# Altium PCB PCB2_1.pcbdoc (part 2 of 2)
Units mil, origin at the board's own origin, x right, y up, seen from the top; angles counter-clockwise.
Board outline 4577.16 x 3522.49 mil, 4 copper layers (Top Layer, Inner1, Inner2, Bottom Layer); 102 components, 86 nets, 382 pads, 182 vias.
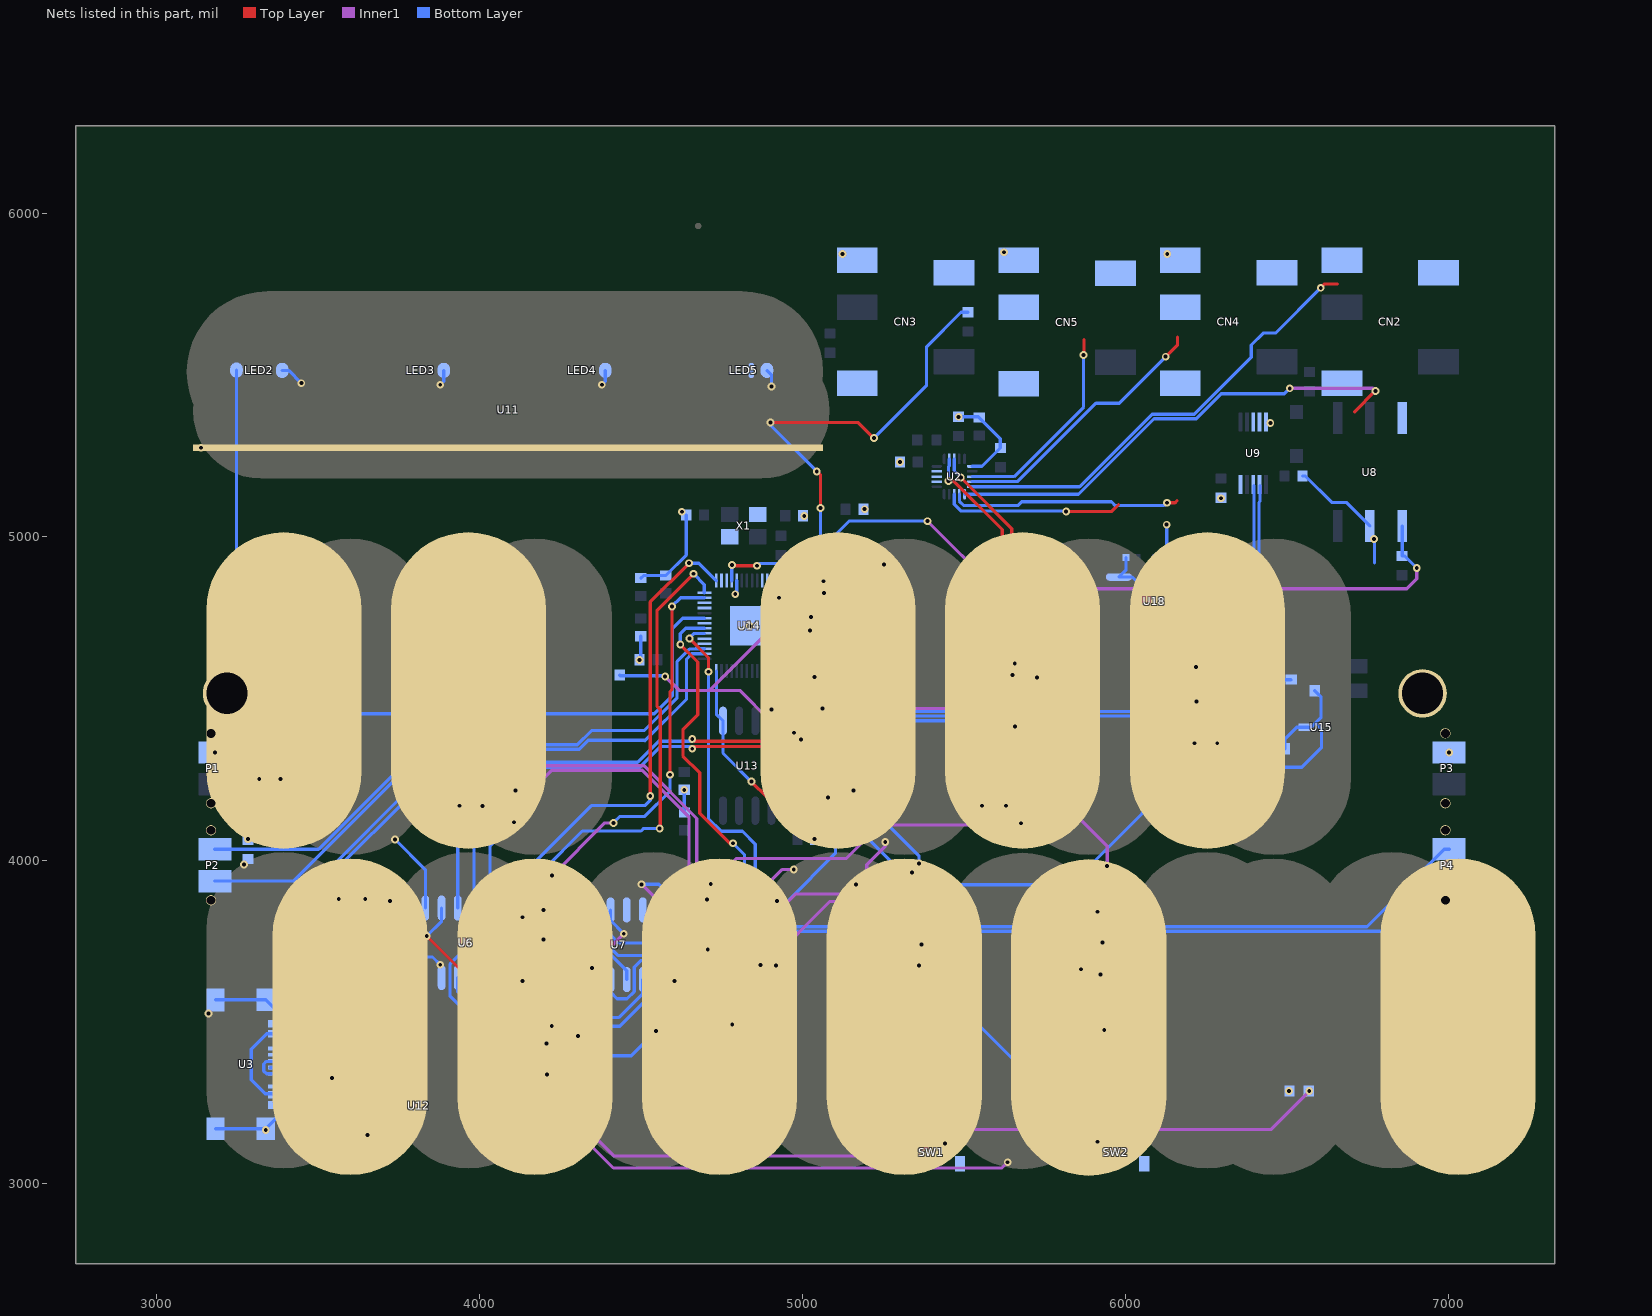
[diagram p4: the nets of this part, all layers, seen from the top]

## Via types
v1: diameter 24.02, hole 12.01, Top Layer to Bottom Layer, 182 vias

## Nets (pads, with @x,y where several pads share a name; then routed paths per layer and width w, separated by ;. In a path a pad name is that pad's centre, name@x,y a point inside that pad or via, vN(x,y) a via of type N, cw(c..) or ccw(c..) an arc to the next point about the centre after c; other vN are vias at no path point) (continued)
ADC-CS-1: U7.10 U14.30 | length 1660.7
  Inner1 w10: v1(4706.64,3722.97) 4770.64,3722.97 v1(4920.64,3872.97)
  Bottom Layer w10: U7.10@4555.64,3630.27 4555.64,3674.07 4604.54,3722.97 v1(4706.64,3722.97) ; v1(4920.64,3872.97) 4953.64,3872.97 5101.64,4020.97 5101.64,4090.97 5090.89,4101.72 5061.25,4101.72 5031.63,4131.34 5031.63,4405.16 5021.63,4415.16 5021.63,4511.77 5067.23,4557.38 5067.23,4769.56 5025.19,4811.59 U14.30@4975.41,4811.59
AS_SIG: K11.2 R28.2 U7.3 | length 2793.5
  Inner1 w10: v1(4501.64,3924.97) 4673.64,3752.97 4673.64,3708.97 4683.64,3698.97 4782.64,3698.97 4978.64,3894.97 5136.64,3894.97 v1(5165.64,3923.97)
  Bottom Layer w10: U7.3@4355.64,3845.67 4355.64,3823.97 4404.64,3774.97 4404.64,3768.43 4429.87,3743.2 4565.31,3743.2 4587.13,3765.01 4635.69,3765.01 4652.64,3781.97 4652.64,3868.97 4625.64,3895.97 4583.64,3895.97 4554.64,3924.97 v1(4501.64,3924.97) ; v1(5165.64,3923.97) 5830.64,3923.97 R28.2@6268.14,4361.46
  other v1: 6283.39,4361.46
B_SIG: K12.2 R27.2 U7.4 | length 3512.9
  Inner1 w10: v1(4446.64,3771.97) 4379.64,3704.97 4075.64,3704.97 4043.64,3672.97 4043.64,3456.97 4416.64,3083.97 5267.64,3083.97 5326.64,3142.97 5399.64,3142.97 5422.64,3165.97 6449.14,3165.97 v1(6568.14,3284.97)
  Bottom Layer w10: U7.4@4405.64,3845.67 4405.64,3812.97 v1(4446.64,3771.97)
BOOT: D3.1 SW2.2 U14.32 | length 2480.7
  Top Layer w10: v1(5036.64,4566.97) 5036.64,4493.97 v1(5061.64,4468.97) ; v1(5912.64,3839.97) 5927.64,3824.97 v1(5927.64,3744.97)
  Inner1 w10: v1(5061.64,4468.97) 5516.64,4468.97 5942.64,4042.97 v1(5942.64,3981.97)
  Bottom Layer w10: U14.32@4975.41,4780.09 5031.52,4780.09 5053.23,4758.38 5053.23,4583.56 v1(5036.64,4566.97) ; v1(5912.64,3839.97) 5942.64,3869.97 v1(5942.64,3981.97) ; v1(5927.64,3744.97) 6034.58,3638.03 6034.58,3215.76 ; D3.1@5980.81,3220.97 6029.38,3220.97 6034.58,3215.76 ; SW2.2@6034.58,3132.09 6034.58,3215.76
C_SIG: K1.2 R21.2 U6.1 | length 305.9
  Bottom Layer w10: v1(3564.64,3878.97) 3623.64,3937.97 3743.64,3937.97 3782.64,3898.97 U6.1@3782.64,3851.67
  other v1: 3271.41,3986.26
CAP0: U2.8 | length 643.8
  Top Layer w10: v1(5869.64,5562.97) 5870.64,5563.97 5870.64,5610.97
  Bottom Layer w10: U2.8@5524.28,5186.97 5654.64,5186.97 5869.64,5401.97 v1(5869.64,5562.97)
CAP1: U2.9 | length 834.9
  Top Layer w10: v1(6123.64,5557.97) 6160.64,5594.97 6160.64,5617.97
  Bottom Layer w10: U2.9@5524.28,5171.22 5664.89,5171.22 5907.64,5413.97 5979.64,5413.97 v1(6123.64,5557.97)
CAP2: U2.10 | length 1412.5
  Top Layer w10: v1(6603.64,5770.97) 6615.64,5782.97 6654.64,5782.97
  Bottom Layer w10: U2.10@5524.28,5155.47 5857.14,5155.47 6081.64,5379.97 6212.64,5379.97 6388.64,5555.97 6388.64,5593.97 6425.64,5630.97 6463.64,5630.97 v1(6603.64,5770.97)
CAP3: U2.11 | length 1502
  Top Layer w10: 6708.64,5386.97 6708.64,5387.97 v1(6772.64,5451.97)
  Inner1 w10: v1(6507.64,5459.97) 6764.64,5459.97 v1(6772.64,5451.97)
  Bottom Layer w10: U2.11@5501.15,5132.34 5853.81,5132.34 6087.44,5365.97 6218.44,5365.97 6295.44,5442.97 6490.64,5442.97 v1(6507.64,5459.97)
CAP4: U2.12 | length 716.5
  Top Layer w10: v1(6127.64,5105.97) 6152.64,5105.97 6158.64,5111.97
  Bottom Layer w10: U2.12@5485.4,5132.34 5485.4,5111.1 5499.53,5096.97 5666.42,5096.97 5678.42,5108.97 5955.9,5108.97 5967.9,5096.97 6118.64,5096.97 v1(6127.64,5105.97)
CAP5: U2.13 | length 557.2
  Top Layer w10: v1(5815.64,5078.97) 5956.64,5078.97 5977.64,5099.97
  Bottom Layer w10: U2.13@5469.65,5132.34 5469.65,5100.96 5490.64,5079.97 5814.64,5079.97 v1(5815.64,5078.97)
CS_SIG: K2.2 R14.2 U6.2 | length 251.2
  Bottom Layer w10: v1(3738.64,4063.97) 3832.64,3969.97 U6.2@3832.64,3851.67
  other v1: 3384.42,4251.29
D+: R35.2 U3.A6 U3.B6 | length 2589.7
  Top Layer w10: v1(4658.64,4374.65) 4665.64,4367.65 4957.33,4367.65 4973.64,4383.97 v1(4973.64,4393.87)
  Bottom Layer w10: U3.B6@3374.57,3397.5 3406.11,3397.5 3417.64,3385.97 3417.64,3364.97 3411.64,3358.97 3375.41,3358.97 U3.A6@3374.57,3358.13 3351.5,3358.11 3351.5,3357.3 3384.57,3357.3 3386,3355.87 3504.64,3355.87 3564.64,3415.87 3564.64,3754.97 3511.95,3807.65 3511.95,3948.91 3805.01,4241.97 4066.64,4241.97 4127.33,4302.65 4489.33,4302.65 4554.33,4367.65 4651.64,4367.65 v1(4658.64,4374.65)
D-: R36.2 U3.A7 U3.B7 | length 2704.7
  Top Layer w10: v1(4658.64,4344.65) 4665.64,4351.65 4963.95,4351.65 4984.95,4372.65 v1(4994.85,4372.65)
  Bottom Layer w10: U3.A7@3374.57,3377.81 3373.73,3376.97 3340.64,3376.97 3332.64,3368.97 3332.64,3346.97 3341.17,3338.44 U3.B7@3374.57,3338.44 3384.57,3338.44 3386,3339.87 3511.27,3339.87 3580.64,3409.24 3580.64,3761.59 3527.95,3814.28 3527.95,3942.28 3811.64,4225.97 4073.27,4225.97 4133.95,4286.65 4495.95,4286.65 4560.95,4351.65 4651.64,4351.65 v1(4658.64,4344.65) ; R36.2@4978.69,4509.92 5002.64,4485.97 5002.64,4380.44 v1(4994.85,4372.65)
D_SIG: K3.2 R15.2 U6.3 | length 544.3
  Top Layer w10: v1(3836.64,3764.97) 4086.64,3514.97 K3.2@4171.64,3514.97
  Bottom Layer w10: v1(3836.64,3764.97) 3882.64,3810.97 U6.3@3882.64,3851.67
  other v1: 3722.64,3872.97
DS_SIG: K4.2 R16.2 U6.4 | length 344.4
  Bottom Layer w10: U6.4@3932.64,3851.67 3932.64,4053.97 3999.8,4121.12 R16.2@3999.8,4168.29
  other v1: 4009.64,4166.97
E_SIG: K5.2 R17.2 U6.5 | length 1388.8
  Inner1 w10: v1(4111.64,4214.97) 4188.64,4291.97 4509.44,4291.97 4672.64,4128.77 4672.64,3909.97 v1(4704.64,3877.97)
  Bottom Layer w10: U6.5@3982.64,3851.67 3982.64,4054.97 4111.64,4183.97 v1(4111.64,4214.97) ; R17.2@4266.55,3432.29 4281.97,3432.29 v1(4304.64,3454.97)
F0: U7.5
F1: U7.6
F2: U7.7
F3: U7.8
F_SIG: K6.2 R18.2 U6.6 | length 1693.2
  Inner1 w10: v1(4106.64,4116.97) 4136.64,4146.97 4136.64,4190.97 4223.63,4277.95 4503.66,4277.95 4648.84,4132.77 4648.84,3873.77 4744.64,3777.97 4937.64,3970.97 v1(4972.64,3970.97)
  Bottom Layer w10: U6.6@4032.64,3851.67 4032.64,4042.97 v1(4106.64,4116.97)
  other v1: 4869.64,3674.97
FS_SIG: K7.2 R19.2 U6.7 | length 2120.4
  Inner1 w10: v1(4546.64,3470.97) 4598.64,3522.97 4716.64,3522.97 4832.64,3638.97 4873.64,3638.97 4893.64,3658.97 4893.64,3681.29 5084.21,3871.86 5147.37,3871.86 5198.5,3922.99 5198.5,3986.15 5255.64,4043.29 v1(5255.64,4055.97)
  Bottom Layer w10: U6.7@4082.64,3851.67 4067.64,3836.67 4067.64,3799.97 4031.64,3799.97 3908.64,3676.97 3908.64,3579.97 4094.33,3394.28 4469.95,3394.28 v1(4546.64,3470.97)
  other v1: 5554.64,4168.29
G_SIG: K8.2 R20.2 U6.8 | length 2218
  Inner1 w10: v1(4132.64,3822.97) 4014.64,3704.97 4014.64,3446.97 4414.64,3046.97 5616.64,3046.97 v1(5634.64,3064.97)
  other v1: 5861.13,3662.04
GND: C1.1 C2.2 C8.1 C9.2 C12.1 C13.1 C14.2 C15.2 C16.2 C17.2 C18.1 C19.1 C20.1 C21.1 C22.1 C23.1 C24.1 C25.1 C27.2 CN3.1 CN4.1 CN5.1 LED2.4 LED3.4 LED4.4 LED5.4 P1.1 P3.1 R1.1 R2.1 R8.1 R9.1 R14.1 R15.1 R16.1 R17.1 R18.1 R19.1 R20.1 R21.1 R22.1 R27.1 R28.1 R29.1 R30.1 R38.1 R39.1 R42.1 SW1.2 SW2.1 U2.6 U3.12 U3.13 U3.14 U3.15 U3.A1B12 U3.A12B1 U6.9 U6.14 U7.9 U7.14 U8.5 U9.10 U11.3 U12.1 U13.4 U14.19 U14.57 U15.2 U18.4 | length 4224.7
  Bottom Layer w10: U3.14@3182.72,3168.36 U3.12@3338.63,3168.36 3374.57,3204.3 U3.A1B12@3374.57,3241.99 ; U3.15@3182.72,3567.57 U3.13@3338.63,3567.58 ; U3.13@3338.63,3567.58 3374.57,3531.64 U3.A12B1@3374.57,3493.96 3431.27,3493.96 R9.1@3448.23,3510.91 ; LED2.4@3389.51,5515.47 3409.14,5515.47 v1(3448.64,5475.97) ; C8.1@3644.64,3467.41 3644.64,3587.97 3756.64,3699.97 3854.64,3699.97 v1(3878.64,3675.97) ; v1(3878.64,5470.97) 3889.51,5481.84 LED3.4@3889.51,5515.47 ; C9.2@4147.2,3312.97 4185.64,3312.97 v1(4208.64,3335.97) ; v1(4378.64,5470.97) 4389.51,5481.84 LED4.4@4389.51,5515.47 ; v1(4495.52,4619.53) 4499.08,4623.09 C19.1@4499.08,4692.53 ; C21.1@4499.64,4872.53 4507.77,4880.65 C20.1@4576.82,4880.65 4640.08,4943.91 C14.2@4640.08,5067.97 ; v1(4633.64,4217.41) 4633.64,4148.07 C23.1@4634.5,4147.21 ; v1(4791.64,4822.97) 4796.27,4827.6 U14.19@4796.27,4864.74 ; LED5.4@4889.51,5515.47 4903.64,5501.34 v1(4903.64,5465.97) ; C17.2@5245.2,4844.97 5245.2,4852.6 C16.2@5181.76,4916.04 5250.57,4916.04 v1(5251.64,4914.97) ; v1(5483.07,5371.78) 5544.39,5371.78 C1.1@5546.64,5369.53 5611.98,5304.19 R1.1@5611.98,5275.29 5555.16,5218.47 U2.6@5524.28,5218.47 ; v1(5650,4572.46) 5626.64,4595.82 5626.64,4618.97 5692.35,4684.68 R42.1@5903.6,4684.68 ; v1(6126.64,5037.97) 6126.87,5037.74 R38.1@6126.87,4936.4 6126.87,4760.74 6161.6,4726 U18.4@6197.39,4726 6209.76,4738.37 R39.1@6271.52,4738.37 ; R28.1@6208.82,4361.46 6254.32,4406.97 6284.64,4406.97 6315.64,4375.97 6315.64,4353.97 6382.64,4286.97 6544.64,4286.97 6605.64,4347.97 6605.64,4406.41 6587.36,4424.69 ; C27.2@6492.02,4344.69 6492.02,4374.34 6528.64,4410.97 U15.2@6554.46,4410.97 6573.64,4410.97 6587.36,4424.69 ; C12.1@6546.82,5188.72 6555.89,5188.72 6637.64,5106.97 6682.83,5106.97 U8.5@6755.64,5034.16 ; C25.1@6585.08,4523.97 6604.64,4504.41 6604.64,4441.97 6587.36,4424.69 ; v1(6768.64,4993.43) 6770.2,4991.87 6770.2,4919.97
  other v1: 5440.64,3123.14 5912.92,3128.25 3654.01,3149.42 3338.64,3164.97 6505.15,3284.97 3543.64,3325.97 4207.23,3432.29 5933.49,3474.46 4782.11,3491.34 3161.46,3524.97 4132.64,3626.29 4603.64,3625.97 5922.38,3646.29 4348.64,3665.97 4918.18,3673.29 3646.64,3878.97 3283.3,4064.8 5037.23,4064.97 3938.64,4168.29 5629.7,4168.29 3318.4,4251.29 3181,4333.29 7001,4333.29 6212.89,4361.46 4903.64,4466.09 4835.64,4724.97 5005.14,5064.97 4626.36,5078.15 5192.02,5085.97 6294.97,5119.77 5301.08,5231.97 3137.87,5275.97 6447.64,5352.97 5123.64,5875.97 6128.64,5875.97 5623.64,5880.97
GS_SIG: K9.2 R22.2 U7.1 | length 1831.1
  Inner1 w10: v1(4715.64,3925.97) 4794.64,4004.97 5135.64,4004.97 5239.64,4108.97 5624.64,4108.97 5629.64,4113.97 v1(5675.64,4113.97)
  Bottom Layer w10: U7.1@4255.64,3845.67 4255.64,3792.97 4254.64,3791.97 4285.63,3760.98 4372.45,3760.98 4428.46,3704.97 4566.72,3704.97 4598.74,3736.98 4669.64,3736.98 4679.64,3746.98 4742.66,3746.98 4751.64,3755.97 4751.64,3889.97 v1(4715.64,3925.97)
  other v1: 5725.64,4564.97
MISO: U6.12 U7.12 U14.15 | length 2191.3
  Top Layer w10: v1(4528.64,4197.97) 4528.64,4798.97 v1(4648.64,4918.97)
  Bottom Layer w10: U6.12@3982.64,3636.27 3982.64,3720.97 4038.64,3776.97 4121.64,3776.97 4174.64,3829.97 ; U7.12@4455.64,3630.27 4455.64,3657.97 4366.64,3746.97 4257.64,3746.97 4174.64,3829.97 ; v1(4528.64,4197.97) 4528.64,4185.25 4512.04,4168.65 4346.32,4168.65 4174.64,3996.97 4174.64,3829.97 ; v1(4648.64,4918.97) 4679.06,4918.97 U14.15@4733.28,4864.74
MOSI: U6.11 U7.11 U14.14 | length 2450.1
  Top Layer w10: v1(4198.64,3753.97) v1(4198.64,3845.97) ; v1(4557.64,4097.97) 4559.66,4099.98 4559.66,4464.97 4549.66,4474.97 4549.66,4772.98 v1(4662.64,4885.97)
  Bottom Layer w10: U6.11@4032.64,3636.27 U6.11@4028.64,3632.27 ; v1(4198.64,3753.97) 4197.64,3752.97 4063.64,3752.97 4028.64,3717.97 U6.11@4028.64,3632.27 ; v1(4198.64,3845.97) 4198.64,3969.97 4318.64,4089.97 4500.29,4089.97 4508.29,4097.97 v1(4557.64,4097.97) ; U7.11@4505.64,3630.27 4505.64,3586.47 4432.14,3512.97 4091.64,3512.97 4028.64,3575.97 U6.11@4028.64,3632.27 ; v1(4662.64,4885.97) 4695.87,4852.74 U14.14@4695.87,4827.34
NEO: LED2.1 U14.9 | length 2605.4
  Bottom Layer w10: LED2.1@3247.78,5516.46 3247.78,4708.83 3503.64,4452.97 4540.64,4452.97 4597.63,4509.95 4597.63,4716.95 4629.28,4748.6 U14.9@4695.87,4748.6
PWR_SENS: U14.11
QCS: R32.2 R34.1 U13.1 U14.56 | length 2064.6
  Top Layer w10: v1(4841.64,4242.97) 4890.64,4193.97 v1(5078.64,4193.97) ; v1(5338.64,3960.97) 5338.64,3945.97 5330.64,3937.97 5330.64,3703.97 v1(5360.64,3673.97)
  Bottom Layer w10: U14.56@4733.28,4585.21 4733.28,4451.31 U13.1@4753.64,4430.95 4753.64,4330.97 v1(4841.64,4242.97) ; v1(5078.64,4193.97) 5078.64,4190.97 5308.64,3960.97 v1(5338.64,3960.97) ; v1(5360.64,3673.97) 5741.64,3292.97 R32.2@5893.98,3292.97 5887.64,3286.63 R34.1@5828.64,3286.63
RST: R7.2 SW1.1 U14.26 | length 2555.8
  Top Layer w10: v1(5360.64,3989.97) 5367.64,3982.97 v1(5367.64,3738.97)
  Inner1 w10: v1(4574.64,4567.97) 4617.64,4524.97 4712.64,4524.97 ; v1(4926.64,4811.97) 4926.64,4738.97 4712.64,4524.97 ; v1(5157.64,4214.97) 5117.64,4254.97 4967.64,4254.97 4900.64,4321.97 4900.64,4429.97 4805.64,4524.97 4712.64,4524.97
  Bottom Layer w10: R7.2@4434.12,4572.11 4436.01,4570.23 4572.38,4570.23 v1(4574.64,4567.97) ; U14.26@4906.5,4864.74 4906.5,4832.11 v1(4926.64,4811.97) ; v1(5157.64,4214.97) 5360.64,4011.97 v1(5360.64,3989.97) ; SW1.1@5332.7,3132.09 5332.7,3704.03 v1(5367.64,3738.97)
RX0: P2.1 U14.3 | length 1837.9
  Bottom Layer w10: P2.1@3181,4033.29 3502.14,4033.29 3825.84,4356.98 4302.86,4356.98 4346.84,4400.97 4510.11,4400.97 4611.64,4502.5 4611.64,4614.97 4649.64,4652.97 4668.07,4652.97 4669.22,4654.11 U14.3@4695.87,4654.11
RX1: P4.2 U14.7 | length 3313.1
  Top Layer w10: v1(4621.64,4666.97) 4675.64,4612.97 4675.64,4449.97 4629.64,4403.97 4629.64,4321.97 4681.64,4269.97 4681.64,4144.97 4774.64,4051.97 v1(4784.64,4051.97)
  Bottom Layer w10: v1(4621.64,4666.97) 4621.64,4700.97 4637.78,4717.1 U14.7@4695.87,4717.1 ; v1(4784.64,4051.97) 4820.11,4016.5 4820.11,3882.5 4922.64,3779.97 6829.64,3779.97 6984.54,3934.87 P4.2@7001,3934.87
RX2: R23.1 U8.4 U14.27 | length 2356.7
  Inner1 w10: v1(5386.64,5048.97) 5595.64,4839.97 6869.64,4839.97 6900.64,4870.97 v1(6900.64,4903.97)
  Bottom Layer w10: U14.27@4922.25,4864.74 4922.25,4891.4 4930.82,4899.97 4994.64,4899.97 5143.64,5048.97 v1(5386.64,5048.97) ; U8.4@6855.64,5034.16 6855.64,4941.31 R23.1@6855.3,4940.97 6863.64,4940.97 v1(6900.64,4903.97)
SCK: U6.13 U7.13 U14.13 | length 2712.2
  Top Layer w10: v1(4223.64,3485.97) 4223.64,3950.97 v1(4224.64,3951.97) ; v1(4589.64,4263.97) 4589.64,4520.97 4595.64,4526.97 v1(4595.64,4784.97)
  Inner1 w10: v1(4224.64,3951.97) 4387.64,4114.97 v1(4414.64,4114.97)
  Bottom Layer w10: U6.13@3932.64,3636.27 3932.64,3592.47 4039.14,3485.97 v1(4223.64,3485.97) 4434.64,3485.97 4528.64,3579.97 4528.64,3672.97 4512.64,3688.97 4498.64,3688.97 4478.64,3668.97 4478.64,3592.97 4456.64,3570.97 4425.64,3570.97 4405.64,3590.97 U7.13@4405.64,3630.27 ; v1(4414.64,4114.97) 4434.86,4135.19 4512.04,4135.19 4589.64,4212.79 v1(4589.64,4263.97) ; v1(4595.64,4784.97) 4622.27,4811.59 4689.23,4811.59 4694.78,4810.78 U14.13@4695.87,4811.59
SCL: R4.2 U2.2 U9.2 U14.35 | length 3796.7
  Top Layer w10: v1(5022.64,4709.97) 5052.64,4739.97 5052.64,4805.97 5066.64,4819.97 v1(5066.64,4825.97) ; v1(5451.64,5172.97) 5467.64,5172.97 5617.64,5022.97 5617.64,4541.97 5657.64,4501.97 v1(5657.64,4413.97)
  Bottom Layer w10: U14.35@4975.41,4732.85 5002.06,4732.85 5022.64,4712.28 v1(5022.64,4709.97) ; v1(5066.64,4825.97) 5124.63,4767.98 5124.63,4466.16 5151.23,4439.56 5151.23,4429.56 5182.82,4397.97 5229.1,4397.97 R4.2@5262.37,4431.23 ; v1(5451.64,5172.97) 5451.64,5218.1 5453.9,5220.36 U2.2@5453.9,5241.6 ; v1@5662.64,4414.97 5656.64,4414.97 5640.37,4431.23 R4.2@5262.37,4431.23 ; U9.2@6415.32,5158.47 6415.32,5109.65 6412.66,5106.98 6412.66,4728.16 6130.45,4445.95 5277.09,4445.95 R4.2@5262.37,4431.23
SDA: R5.2 U2.3 U9.3 U14.34 | length 3313.9
  Top Layer w10: v1(5025.64,4751.97) 5017.64,4759.97 5017.64,4815.97 v1(5064.64,4862.97) ; v1(5489.64,5183.97) 5647.64,5025.97 5647.64,4616.97 v1(5656.64,4607.97)
  Bottom Layer w10: U14.34@4975.41,4748.6 5022.28,4748.6 v1(5025.64,4751.97) ; v1(5064.64,4862.97) 5138.64,4788.97 5138.64,4471.97 5179.67,4430.94 R5.2@5197.37,4430.94 ; R5.2@5199.37,4430.94 R5.2@5197.37,4430.94 ; U2.3@5469.65,5241.6 5469.65,5203.96 v1(5489.64,5183.97) ; v1(5656.64,4607.97) 5673.65,4607.97 5679.64,4601.97 5679.64,4460.61 5678.99,4459.97 ; U9.3@6396.64,5159.47 6396.64,4733.97 6122.64,4459.97 5678.99,4459.97 ; R5.2@5197.37,4430.94 5226.4,4459.97 5678.99,4459.97
TX0: P2.2 U14.2 | length 1880.1
  Bottom Layer w10: P2.2@3181,3934.87 3423.54,3934.87 3831.64,4342.97 4308.64,4342.97 4336.64,4370.97 4510.51,4370.97 4512.04,4369.44 4640.64,4498.04 4640.64,4621.97 4657.04,4638.36 U14.2@4695.87,4638.36
TX1: P4.1 U14.6 | length 3270.6
  Top Layer w10: v1(4649.64,4685.97) 4708.64,4626.97 v1(4708.64,4582.97)
  Bottom Layer w10: v1(4649.64,4685.97) 4665.03,4701.35 U14.6@4695.87,4701.35 ; v1(4708.64,4582.97) 4708.64,4127.97 4747.64,4088.97 4814,4088.97 4853.57,4049.4 4853.57,3868.86 4928.45,3793.98 6746.66,3793.98 6985.96,4033.29 P4.1@7001,4033.29
TX2: R26.2 U14.18 | length 1645.5
  Top Layer w10: v1(4781.64,4912.97) 4783.64,4910.97 v1(4858.64,4910.97) ; v1(4900.64,5353.97) 5172.64,5353.97 v1(5220.64,5305.97) ; v1(5043.64,5202.97) 5055.64,5190.97 v1(5055.64,5089.97)
  Bottom Layer w10: U14.18@4780.52,4864.74 4780.52,4911.85 v1(4781.64,4912.97) ; v1(4858.64,4910.97) 4865.11,4917.43 4980.11,4917.43 5055.64,4992.97 v1(5055.64,5089.97) ; v1(4900.64,5353.97) 4900.64,5345.97 v1(5043.64,5202.97) ; v1(5220.64,5305.97) 5383.64,5468.97 5383.64,5588.73 5490.16,5695.25 R26.2@5512.16,5695.25
VHI: C26.1 C27.1 D4.1 R43.2 U18.8 | length 1088.6
  Top Layer w10: v1(6217.64,4597.97) 6218.64,4596.97 v1(6218.64,4490.97)
  Bottom Layer w10: R43.2@6001.2,4936 6001.2,4898.11 U18.8@5979.09,4876 6019.6,4876 6086.64,4808.97 6086.64,4728.97 v1(6217.64,4597.97) ; v1(6218.64,4490.97) 6249.95,4459.66 6436.9,4459.66 ; C27.1@6436.9,4344.69 6436.9,4459.66 ; C26.1@6511.68,4558.63 6511.01,4557.97 D4.1@6450.81,4557.97 6436.9,4544.06 6436.9,4459.66
VUSB: C8.2 U3.A4B9 U3.A9B4 U12.3 | length 742.1
  Bottom Layer w10: U3.A9B4@3374.57,3462.46 3341.03,3462.46 3293.64,3415.07 3293.64,3319.97 3336.59,3277.01 3371.03,3277.01 U3.A4B9@3374.57,3273.48 3637.67,3273.48 U12.3@3694.71,3330.52 3644.64,3380.59 C8.2@3644.64,3412.29
"": CN2.1 CN2.2 CN2.5 CN3.2 CN3.5 CN4.2 CN4.3 CN4.5 CN5.2 CN5.3 CN5.5 LED5.3 P1.3 P1.4 P2.3 P2.4 P3.3 P3.4 P4.3 P4.4 pad.73 SW1.3 SW1.4 SW2.3 SW2.4 U2.17 U2.18 U2.19 U3.A8 U3.B8 U8.3 U9.5 U9.8 U9.9 U14.4 U14.5 U14.8 U14.12 U14.16 U14.17 U14.24 U14.25 U14.28 U14.31 U14.36 U14.37 U14.39 U14.40 U14.41 X1.2 X1.4

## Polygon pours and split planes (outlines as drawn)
GND on Inner2 (split plane): 7058.54,3113.97 cw(c7013.59,3069.02) 6968.64,3024.07 3168.64,3024.07 cw(c3123.69,3069.02) 3078.74,3113.97 3078.74,5913.97 cw(c3123.69,5958.92) 3168.64,6003.87 6968.64,6003.87 cw(c7013.59,5958.92) 7058.54,5913.97 7058.54,3113.97

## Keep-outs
Inner2:
  region net "": 4987.64,5901.97 4985.64,5901.97 4920.64,5966.97 4746.64,5966.97 4721.64,5941.97 3166.64,5941.97 3107.64,5882.97 3107.64,5686.97 3189.64,5604.97 4965.64,5604.97 4990.64,5629.97
Board Outline Layer:
  lines w10 net "": 3068.64,3113.97 ccw(c3168.64,3113.97) 3168.64,3013.97 6968.64,3013.97 ccw(c6968.64,3113.97) 7068.64,3113.97 7068.64,5913.97 ccw(c6968.64,5913.97) 6968.64,6013.97 3168.64,6013.97 ccw(c3168.64,5913.97) 3068.64,5913.97 3068.64,3113.97

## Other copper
Top Layer:
  region net CAP0: 5985.46,5941.74 5961.13,5850.92 cw(c5808.69,5764.97) 5722.74,5612.53 5631.91,5588.19 5656.25,5679.02 cw(c5808.69,5764.97) 5894.64,5917.41
  region net CAP5: 5991.19,5090.97 5641.19,5265.97 5991.19,5440.97 5916.19,5265.97
  region net CAP4: 6141.19,5090.97 6316.19,5440.97 6491.19,5090.97 6316.19,5165.97
  region net CAP3: 6641.19,5440.97 6716.19,5265.97 6641.19,5090.97 6991.19,5265.97
  region net "": 6611.19,5500.97 7036.19,5500.97 ccw(c7036.19,5515.97) 7036.19,5530.97 6611.19,5530.97 ccw(c6611.19,5515.97)
  region net "": 6551.19,5985.97 6551.19,5045.97 ccw(c6566.19,5045.97) 6581.19,5045.97 6581.19,5985.97 ccw(c6566.19,5985.97)
  region net "": 6521.19,5530.97 6111.19,5530.97 ccw(c6111.19,5515.97) 6111.19,5500.97 6521.19,5500.97 ccw(c6521.19,5515.97)
  region net "": 5596.19,5530.97 6021.19,5530.97 cw(c6021.19,5515.97) 6021.19,5500.97 5596.19,5500.97 cw(c5596.19,5515.97)
  region net "": 6051.19,5985.97 6051.19,5045.97 ccw(c6066.19,5045.97) 6081.19,5045.97 6081.19,5985.97 ccw(c6066.19,5985.97)
  region net CAP1: 6137.18,5586.52 6317.77,5624.64 6494.59,5587.15 6493.64,5805.97 6411.64,5955.97 6317.84,5996.93 6223.94,5957.85 6136.66,5799.08
  region net CAP2: 6791.19,5940.7 6791.19,5940.97 6641.19,5940.97 6641.19,5590.97 6818.64,5590.97 6992.64,5765.97 6804.9,5940.7
  region net $1N16825: 3916.14,5550.97 cw(c3916.14,5555.97) 3912.3,5552.77 3888.8,5580.97 3873.21,5580.97 3864.68,5572.43 cw(c3861.14,5575.97) 3861.14,5570.97 3314.89,5570.97 cw(c3314.89,5575.97) 3310.89,5572.97 3297.39,5590.97 3256.14,5590.97 3256.14,5940.97 3306.14,5940.97 3306.14,5595.97 3317.39,5580.97 3859.07,5580.97 3867.61,5589.5 cw(c3871.14,5585.97) 3871.14,5590.97 3856.14,5590.97 3856.14,5940.97 3906.14,5940.97 3906.14,5590.97 3891.14,5590.97 cw(c3891.14,5585.97) 3894.98,5589.17 3918.48,5560.97 4433.64,5560.97 4456.14,5590.97 4456.14,5940.97 4506.14,5940.97 4506.14,5590.97 4468.64,5590.97 4440.14,5552.97 cw(c4436.14,5555.97) 4436.14,5550.97
  region net $1N16823: 4106.14,5940.97 4106.14,5590.97 4056.14,5590.97 4056.14,5940.97 4076.14,5940.97 cw(c4076.14,5945.97) 4072.61,5942.43 4044.07,5970.97 3544.51,5970.97 3506.14,5929.02 3506.14,5590.97 3456.14,5590.97 3456.14,5940.97 3503.51,5940.97 3538.62,5979.34 cw(c3542.31,5975.97) 3542.31,5980.97 4046.14,5980.97 cw(c4046.14,5975.97) 4049.68,5979.5 4078.21,5950.97 4089.07,5950.97 4117.61,5979.5 cw(c4121.14,5975.97) 4121.14,5980.97 4627.52,5980.97 cw(c4627.52,5975.97) 4631.11,5979.45 4668.41,5940.97 4706.14,5940.97 4706.14,5590.97 4656.14,5590.97 4656.14,5939.26 4625.41,5970.97 4123.21,5970.97 4094.68,5942.43 cw(c4091.14,5945.97) 4091.14,5940.97
  region net $1N16821: 4641.14,5570.97 cw(c4641.14,5575.97) 4636.14,5575.97 4636.14,5933.9 4619.07,5950.97 4323.21,5950.97 4306.14,5933.9 4306.14,5590.97 4286.14,5590.97 cw(c4281.14,5590.97) 4284.68,5587.43 4269.68,5572.43 cw(c4266.14,5575.97) 4266.14,5570.97 4051.14,5570.97 cw(c4051.14,5575.97) 4047.61,5572.43 4037.61,5582.43 cw(c4041.14,5585.97) 4036.14,5585.97 4036.14,5943.9 4029.07,5950.97 3723.21,5950.97 3709.68,5937.43 cw(c3706.14,5940.97) 3706.14,5935.97 3706.14,5590.97 3656.14,5590.97 3656.14,5940.97 3701.14,5940.97 cw(c3706.14,5940.97) 3702.61,5944.5 3717.61,5959.5 cw(c3721.14,5955.97) 3721.14,5960.97 4031.14,5960.97 cw(c4031.14,5955.97) 4034.68,5959.5 4044.68,5949.5 cw(c4041.14,5945.97) 4046.14,5945.97 4046.14,5588.04 4053.21,5580.97 4264.07,5580.97 4274.07,5590.97 4256.14,5590.97 4256.14,5940.97 4299.07,5940.97 4317.61,5959.5 cw(c4321.14,5955.97) 4321.14,5960.97 4621.14,5960.97 cw(c4621.14,5955.97) 4624.68,5959.5 4644.68,5939.5 cw(c4641.14,5935.97) 4646.14,5935.97 4646.14,5580.97 4844.07,5580.97 4856.14,5593.04 4856.14,5940.97 4906.14,5940.97 4906.14,5590.97 4868.21,5590.97 4849.68,5572.43 cw(c4846.14,5575.97) 4846.14,5570.97

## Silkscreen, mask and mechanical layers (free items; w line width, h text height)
Bottom Silkscreen Layer:
  text "S-12 Pupnik Controller" at 4618.64,5281.97 h120
  text "RP2040 Version (No BLE/Battery)" at 4454.82,5222.97 h60
  text "Designed in Seattle, USA" at 4438.76,5141.97 h80
  text "CC-BY-SA 4.0 Tori 2024" at 4301.64,5074.97 h60
Top Solder Mask Layer:
  region net "": 6551.19,5985.97 6551.19,5045.97 ccw(c6566.19,5045.97) 6581.19,5045.97 6581.19,5985.97 ccw(c6566.19,5985.97)
  region net "": 6051.19,5985.97 6051.19,5045.97 ccw(c6066.19,5045.97) 6081.19,5045.97 6081.19,5985.97 ccw(c6066.19,5985.97)
  region net "": 6611.19,5500.97 7036.19,5500.97 ccw(c7036.19,5515.97) 7036.19,5530.97 6611.19,5530.97 ccw(c6611.19,5515.97)
  region net "": 5596.19,5530.97 6021.19,5530.97 cw(c6021.19,5515.97) 6021.19,5500.97 5596.19,5500.97 cw(c5596.19,5515.97)
  region net "": 6521.19,5530.97 6111.19,5530.97 ccw(c6111.19,5515.97) 6111.19,5500.97 6521.19,5500.97 ccw(c6521.19,5515.97)
  region net "": 6141.19,5090.97 6316.19,5440.97 6491.19,5090.97 6316.19,5165.97
  region net "": 5991.19,5090.97 5641.19,5265.97 5991.19,5440.97 5916.19,5265.97
  region net "": 6641.19,5440.97 6716.19,5265.97 6641.19,5090.97 6991.19,5265.97
  region net "": 5985.46,5942.74 5961.13,5851.92 cw(c5808.69,5765.97) 5722.74,5613.53 5631.91,5589.19 5656.25,5680.02 cw(c5808.69,5765.97) 5894.64,5918.41
  region net "": 6141.19,5706.15 6218.69,5794.72 6218.69,5944.72 6141.19,5806.15
  region net "": 6228.69,5957.75 6306.19,5990.97 6306.19,5835.06 6228.69,5801.85
  region net "": 6413.69,5944.72 6491.19,5806.15 6491.19,5706.15 6413.69,5794.72
  region net "": 6641.19,5940.97 6691.19,5940.97 6691.19,5590.97 6641.19,5590.97
  region net "": 6716.19,5940.97 6766.19,5940.97 6766.19,5590.97 6716.19,5590.97
  region net "": 6791.19,5940.97 6991.19,5765.97 6791.19,5590.97 6866.19,5765.97
  region net "": 6141.19,5589 cw(c6141.19,5590.97) 6139.22,5590.97 6139.22,5690.97 cw(c6141.19,5690.97) 6139.71,5692.26 6227.21,5792.26 cw(c6228.69,5790.97) 6227.91,5792.78 6315.41,5830.28 cw(c6316.19,5828.47) 6316.19,5830.44 cw(c6316.19,5828.47) 6316.96,5830.28 6404.46,5792.78 cw(c6403.69,5790.97) 6405.17,5792.26 6492.67,5692.26 cw(c6491.19,5690.97) 6493.15,5690.97 6493.15,5590.97 cw(c6491.19,5590.97) 6491.19,5589 cw(c6491.19,5590.97) 6490.77,5589.04 6316.19,5626.45 6141.6,5589.04 cw(c6141.19,5590.97)
  region net "": 6326.19,5835.06 6326.2,5835.08 6326.19,5990.97 6403.69,5957.75 6403.69,5801.85
Bottom Solder Mask Layer:
  region net "": 3118.64,5615.97 5043.64,5615.97 5043.64,5915.97 3118.64,5915.97
Mech6:
  circle w3.94 net "": c3247.21,4515.97 r62.99
  circle w3.94 net "": c6890.07,4515.97 r62.99
  lines w3.94 net "": 3068.64,5015.97 7068.64,5015.97 ; 3104.36,3039.37 3104.36,5015.97 ; 3168.64,3015.97 6968.64,3015.97 ; 3390.07,5015.97 3390.07,4015.97 3890.07,4015.97 3890.07,5015.97 ; 3604.36,3015.97 3604.36,4015.97 ; 3675.78,3015.97 3675.78,4015.97 ; 3961.5,5015.97 3961.5,4015.97 4461.5,4015.97 4461.5,5015.97 ; 4175.78,3015.97 4175.78,4015.97 ; 4247.21,3015.97 4247.21,4015.97 ; 4747.21,3015.97 4747.21,4015.97 4747.21,5015.97 ; 4818.64,3015.97 4818.64,4015.97 4818.64,5015.97 ; 5104.36,5015.97 5104.36,4015.97 5604.36,4015.97 5604.36,5015.97 ; 5318.64,3015.97 5318.64,4015.97 ; 5390.07,3015.97 5390.07,4015.97 ; 5675.78,5015.97 5675.78,4015.97 6175.78,4015.97 6175.78,5015.97 ; 5890.07,3015.97 5890.07,4015.97 ; 5961.5,3015.97 5961.5,4015.97 ; 6247.21,5015.97 6247.21,4015.97 6747.21,4015.97 6747.21,5015.97 ; 6461.5,3015.97 6461.5,4015.97 ; 6532.93,3015.97 6532.93,4015.97 ; 7032.93,3039.37 7032.93,5015.97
